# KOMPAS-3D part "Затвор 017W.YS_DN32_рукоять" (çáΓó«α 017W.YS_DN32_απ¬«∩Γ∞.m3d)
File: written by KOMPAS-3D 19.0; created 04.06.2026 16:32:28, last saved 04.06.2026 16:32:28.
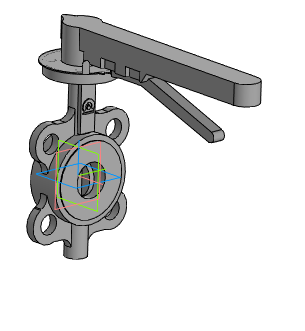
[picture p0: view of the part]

Document properties: Автор: Энергия; Полное имя файла: ..\..\..\3d для проектировщиков\017W разные\x.x Тип 017W.Y(S) Затвор дисковый поворотный межфланцевый\Затвор 017W.Y(S)_DN32-DN300_рукоять\Затвор 017W.YS_DN32_рукоять.a3d

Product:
- Part/product: Затвор 017W.YS_DN32_рукоять
    Масса: 3.08243

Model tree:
1. Операция без истории:1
